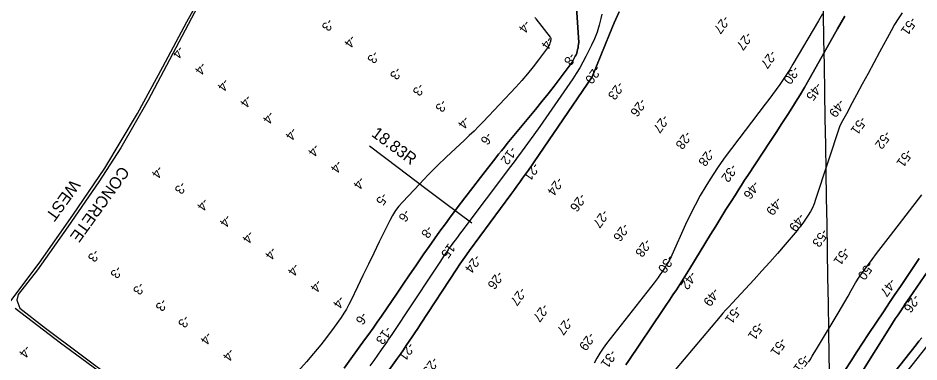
# Model space of a CAD drawing. Extents: x 3879599 to 3900814, y 146526 to 168888.
# Drawn here: x 3891140 to 3894369, y 158633 to 159864 of the extents above; entities that cross this region are included whole.
import ezdxf

# ---------------------------------------------------------------- set-up
doc = ezdxf.new("R2010")
doc.units = 0
for name, color, linetype in [('V-GRID-MAJR', 7, 'Continuous'), ('V-LEVE-TOET', 7, 'Continuous'), ('V-RIVR-JETY', 7, 'Continuous'), ('V-RIVR-RANG', 7, 'Continuous'), ('V-STRM-FMON', 7, 'Continuous'), ('V-TOPO-DPTH', 7, 'Continuous'), ('V-TOPO-MAJR', 7, 'Continuous'), ('V-TOPO-MINR', 7, 'Continuous')]:
    doc.layers.add(name, color=color, linetype=linetype)

msp = doc.modelspace()

# ---------------------------------------------------------------- linework, layer by layer
at = {"layer": 'V-GRID-MAJR'}
msp.add_spline([(3894134.7, 153416.7), (3894080.4, 156663.6), (3893979, 162723.9), (3893946.7, 164659.1)], degree=3, dxfattribs=at)
at = {"layer": 'V-LEVE-TOET'}
msp.add_lwpolyline([(3892766.9, 159129.2), (3892668.1, 159203), (3892601.4, 159252), (3892503, 159328.2), (3892400.2, 159404.9)], dxfattribs=at)
at = {"layer": 'V-RIVR-JETY'}
for points in [[(3890311.8, 157772.1), (3890351.4, 157824), (3890391.9, 157878.3), (3890469.7, 157970.5), (3890554, 158087), (3890601.4, 158142.3), (3890711.2, 158292.3), (3890848.1, 158493.3), (3890978.8, 158672.5), (3891093.1, 158822.5), (3891215.9, 158985.9), (3891337.2, 159158.7), (3891451.6, 159326.6), (3891568.1, 159522.2), (3891659.2, 159689.7), (3891745.2, 159850.3), (3891815.3, 159977.8)], [(3891795.7, 159927.3), (3891716.1, 159777.6), (3891607, 159570.1), (3891508.5, 159399.1), (3891430.5, 159277.6), (3891318.7, 159116.7), (3891209.8, 158962.1), (3891141.4, 158873.8), (3891135.9, 158853.5), (3891147.1, 158824.7), (3891238.4, 158753.9), (3891490.2, 158565.7), (3891632.8, 158455.9), (3891627.8, 158448.5), (3891486.2, 158557.8), (3891292.7, 158700.1), (3891130.8, 158823.8)]]:
    msp.add_lwpolyline(points, dxfattribs=at)
at = {"layer": 'V-TOPO-DPTH'}
for points in [[(3892308.5, 158610.4), (3892333.3, 158643.9), (3892382.5, 158711.3), (3892397.8, 158732.5), (3892413, 158753.8), (3892427.9, 158775.3), (3892442.7, 158796.9), (3892498.6, 158879.1), (3892520.8, 158911.7), (3892543, 158944.2), (3892565.3, 158976.6), (3892587.6, 159009.1), (3892594.7, 159019.4), (3892613.7, 159046.5), (3892632.8, 159073.6), (3892652.2, 159100.5), (3892671.7, 159127.2), (3892686.7, 159147.6), (3892714, 159184.4), (3892741.6, 159220.9), (3892769.5, 159257.3), (3892797.5, 159293.4), (3892852.2, 159363.2), (3892862.5, 159376.2), (3892872.8, 159389.1), (3892883.2, 159401.9), (3892893.6, 159414.6), (3892995.1, 159537.3), (3893017.5, 159564.8), (3893039.7, 159592.5), (3893061.5, 159620.6), (3893083.1, 159648.8), (3893119, 159696.5), (3893122.3, 159701.1), (3893125.5, 159705.8), (3893128.4, 159710.7), (3893131.1, 159715.6), (3893137.3, 159727.3), (3893140, 159733), (3893142.4, 159738.9), (3893144.2, 159745), (3893145.7, 159751.2), (3893146.9, 159757.5), (3893147.9, 159763.9), (3893148.7, 159770.2), (3893149.3, 159776.6), (3893127.6, 160119)], [(3893293.9, 159887), (3893276.9, 159847), (3893260.2, 159806.9), (3893197.7, 159653.6), (3892990.3, 159349.7), (3892980, 159334.8), (3892969.7, 159320), (3892959.2, 159305.3), (3892948.6, 159290.7), (3892937.9, 159276.2), (3892927.2, 159261.6), (3892916.6, 159247.1), (3892905.9, 159232.5), (3892758.5, 159031.9), (3892746.8, 159015.8), (3892735.3, 158999.5), (3892724.1, 158983.1), (3892713, 158966.6), (3892582.6, 158768.2), (3892572.5, 158752.8), (3892562.3, 158737.4), (3892552.2, 158722), (3892542, 158706.6), (3892531.8, 158691.3), (3892521.4, 158676.1), (3892510.9, 158661), (3892500.2, 158645.9), (3892307.5, 158376.6)], [(3892307.5, 158376.6), (3892500.2, 158645.9), (3892510.9, 158661), (3892521.4, 158676.1), (3892531.8, 158691.3), (3892542, 158706.6), (3892552.2, 158722), (3892562.3, 158737.4), (3892572.5, 158752.8), (3892582.6, 158768.2), (3892713, 158966.6), (3892724.1, 158983.1), (3892735.3, 158999.5), (3892746.8, 159015.8), (3892758.5, 159031.9), (3892905.9, 159232.5), (3892916.6, 159247.1), (3892927.2, 159261.6), (3892937.9, 159276.2), (3892948.6, 159290.7), (3892959.2, 159305.3), (3892969.7, 159320), (3892980, 159334.8), (3892990.3, 159349.7), (3893197.7, 159653.6), (3893260.2, 159806.9), (3893276.9, 159847), (3893293.9, 159887)], [(3894023.5, 159879.5), (3894009, 159854.8), (3893916.9, 159698.5), (3893905.6, 159680), (3893894, 159661.6), (3893881.9, 159643.6), (3893869.6, 159625.7), (3893856.9, 159608.1), (3893844.1, 159590.5), (3893831.2, 159573.1), (3893818.1, 159555.7), (3893674.7, 159366.6), (3893660.4, 159347.2), (3893646.5, 159327.5), (3893633.3, 159307.4), (3893620.4, 159287), (3893604.9, 159261.8), (3893585.2, 159228.3), (3893566.4, 159194.3), (3893549, 159159.6), (3893532.4, 159124.5), (3893483.2, 159014.9), (3893480.4, 159009), (3893477.5, 159003.2), (3893474.4, 158997.4), (3893471.1, 158991.7), (3893466.4, 158983.7), (3893464.4, 158980.4), (3893462.4, 158977.2), (3893460.3, 158974), (3893459.7, 158973), (3893459.1, 158972.1), (3893447.2, 158954.4), (3893440.6, 158944.7), (3893433.8, 158935), (3893426.8, 158925.6), (3893419.6, 158916.2), (3893249.2, 158698.6), (3893236.8, 158681.8), (3893225, 158664.5), (3893214.3, 158646.6), (3893204.3, 158628.3)], [(3894023.5, 159879.5), (3894009, 159854.8), (3893916.9, 159698.5), (3893905.6, 159680), (3893894, 159661.6), (3893881.9, 159643.6), (3893869.6, 159625.7), (3893856.9, 159608.1), (3893844.1, 159590.5), (3893831.2, 159573.1), (3893818.1, 159555.7), (3893674.7, 159366.6), (3893660.4, 159347.2), (3893646.5, 159327.5), (3893633.3, 159307.4), (3893620.4, 159287), (3893604.9, 159261.8), (3893585.2, 159228.3), (3893566.4, 159194.3), (3893549, 159159.6), (3893532.4, 159124.5), (3893483.2, 159014.9), (3893480.4, 159009), (3893477.5, 159003.2), (3893474.4, 158997.4), (3893471.1, 158991.7), (3893466.4, 158983.7), (3893464.4, 158980.4), (3893462.4, 158977.2), (3893460.3, 158974), (3893459.7, 158973), (3893459.1, 158972.1), (3893447.2, 158954.4), (3893440.6, 158944.7), (3893433.8, 158935), (3893426.8, 158925.6), (3893419.6, 158916.2), (3893249.2, 158698.6), (3893236.8, 158681.8), (3893225, 158664.5), (3893214.3, 158646.6), (3893204.3, 158628.3)], [(3893317.9, 158622.4), (3893328.5, 158638.1), (3893449.6, 158816.4), (3893462.2, 158835), (3893474.6, 158853.7), (3893487, 158872.4), (3893499.3, 158891.2), (3893511.4, 158910.1), (3893523.4, 158929), (3893535.3, 158948), (3893547.1, 158967.1), (3893621.9, 159089.4), (3893640.2, 159119), (3893658.5, 159148.6), (3893676.9, 159178), (3893695.4, 159207.4), (3893710.7, 159231.5), (3893721.7, 159248.8), (3893732.8, 159266), (3893744, 159283.2), (3893755.3, 159300.3), (3893836, 159422.4), (3893856.9, 159454.3), (3893877.7, 159486.4), (3893898.2, 159518.6), (3893918.6, 159550.9), (3893926, 159562.7), (3893942.4, 159589.3), (3893958.5, 159616.1), (3893974.2, 159643), (3893989.7, 159670.1), (3894077.2, 159825.8), (3894089.9, 159848.4), (3894102.8, 159871)], [(3893317.9, 158622.4), (3893328.5, 158638.1), (3893449.6, 158816.4), (3893462.2, 158835), (3893474.6, 158853.7), (3893487, 158872.4), (3893499.3, 158891.2), (3893511.4, 158910.1), (3893523.4, 158929), (3893535.3, 158948), (3893547.1, 158967.1), (3893621.9, 159089.4), (3893640.2, 159119), (3893658.5, 159148.6), (3893676.9, 159178), (3893695.4, 159207.4), (3893710.7, 159231.5), (3893721.7, 159248.8), (3893732.8, 159266), (3893744, 159283.2), (3893755.3, 159300.3), (3893836, 159422.4), (3893856.9, 159454.3), (3893877.7, 159486.4), (3893898.2, 159518.6), (3893918.6, 159550.9), (3893926, 159562.7), (3893942.4, 159589.3), (3893958.5, 159616.1), (3893974.2, 159643), (3893989.7, 159670.1), (3894077.2, 159825.8), (3894089.9, 159848.4), (3894102.8, 159871)], [(3894113.3, 158516.1), (3894264.7, 158756.5), (3894274.2, 158771.5), (3894283.8, 158786.5), (3894293.5, 158801.4), (3894303.2, 158816.2), (3894311.7, 158829), (3894317.3, 158837.4), (3894322.9, 158845.8), (3894328.6, 158854.2), (3894334.2, 158862.5), (3894544.4, 159168.1)], [(3894544.4, 159168.1), (3894334.2, 158862.5), (3894328.6, 158854.2), (3894322.9, 158845.8), (3894317.3, 158837.4), (3894311.7, 158829), (3894303.2, 158816.2), (3894293.5, 158801.4), (3894283.8, 158786.5), (3894274.2, 158771.5), (3894264.7, 158756.5), (3894113.3, 158516.1)], [(3894105.7, 158605.8), (3894125.9, 158637.1), (3894146.1, 158668.4), (3894166.5, 158699.5), (3894187.1, 158730.6), (3894244, 158816.2), (3894263.2, 158845.1), (3894282.5, 158873.9), (3894301.9, 158902.8), (3894321.3, 158931.5), (3894325.8, 158938.3), (3894347.4, 158970.5), (3894368.8, 159002.8)], [(3894368.8, 159002.8), (3894347.4, 158970.5), (3894325.8, 158938.3), (3894321.3, 158931.5), (3894301.9, 158902.8), (3894282.5, 158873.9), (3894263.2, 158845.1), (3894244, 158816.2), (3894187.1, 158730.6), (3894166.5, 158699.5), (3894146.1, 158668.4), (3894125.9, 158637.1), (3894105.7, 158605.8)], [(3894378.3, 158719.5), (3894368.2, 158706.8), (3894358.2, 158694), (3894196.5, 158488.7)], [(3894378.3, 158719.5), (3894368.2, 158706.8), (3894358.2, 158694), (3894196.5, 158488.7)]]:
    msp.add_lwpolyline(points, dxfattribs=at)
at = {"layer": 'V-TOPO-MAJR'}
for points in [[(3894308.1, 159882.7), (3894294, 159862), (3894280.9, 159840.7), (3894268.5, 159818.9), (3894227, 159741.7), (3894206.5, 159703.6), (3894186, 159665.4), (3894165.5, 159627.3), (3894145.1, 159589.1), (3894122.6, 159547.2), (3894113.4, 159530), (3894104.1, 159512.8), (3894094.8, 159495.7), (3894085.4, 159478.5), (3893997.6, 159214.4), (3893992.9, 159199.4), (3893987.2, 159184.9), (3893980, 159171.1), (3893971.8, 159157.8), (3893952.5, 159130.1), (3893947.7, 159123.3), (3893942.7, 159116.7), (3893937.5, 159110.2), (3893932.2, 159103.8), (3893888.8, 159053), (3893861.5, 159021.4), (3893833.9, 158990.1), (3893805.9, 158959.1), (3893777.7, 158928.4), (3893699, 158843.7), (3893688, 158831.7), (3893677.1, 158819.6), (3893666.4, 158807.3), (3893655.8, 158794.9), (3893495.5, 158604.8)], [(3893972.7, 158631.3), (3893978.4, 158640.7), (3893986, 158653.2), (3893993.5, 158665.6), (3894001, 158678.1), (3894008.5, 158690.6), (3894078.7, 158807.9), (3894090.7, 158828.1), (3894102.6, 158848.3), (3894114.4, 158868.6), (3894126.1, 158889), (3894141.4, 158915.6), (3894145.5, 158922.6), (3894149.8, 158929.5), (3894154.2, 158936.3), (3894158.8, 158943), (3894163.4, 158949.6), (3894165.8, 158952.9), (3894168.1, 158956.2), (3894170.5, 158959.5), (3894173, 158962.8), (3894200.5, 158999.5), (3894216.8, 159021.1), (3894233.1, 159042.7), (3894249.5, 159064.2), (3894266.1, 159085.6), (3894378.5, 159230.8)]]:
    msp.add_lwpolyline(points, dxfattribs=at)
at = {"layer": 'V-TOPO-MINR'}
for points in [[(3893127.6, 160119), (3893149.3, 159776.6), (3893148.7, 159770.2), (3893147.9, 159763.9), (3893146.9, 159757.5), (3893145.7, 159751.2), (3893144.2, 159745), (3893142.4, 159738.9), (3893140, 159733), (3893137.3, 159727.3), (3893131.1, 159715.6), (3893128.4, 159710.7), (3893125.5, 159705.8), (3893122.3, 159701.1), (3893119, 159696.5), (3893083.1, 159648.8), (3893061.5, 159620.6), (3893039.7, 159592.5), (3893017.5, 159564.8), (3892995.1, 159537.3), (3892893.6, 159414.6), (3892883.2, 159401.9), (3892872.8, 159389.1), (3892862.5, 159376.2), (3892852.2, 159363.2), (3892797.5, 159293.4), (3892769.5, 159257.3), (3892741.6, 159220.9), (3892714, 159184.4), (3892686.7, 159147.6), (3892671.7, 159127.2), (3892652.2, 159100.5), (3892632.8, 159073.6), (3892613.7, 159046.5), (3892594.7, 159019.4), (3892587.6, 159009.1), (3892565.3, 158976.6), (3892543, 158944.2), (3892520.8, 158911.7), (3892498.6, 158879.1), (3892442.7, 158796.9), (3892427.9, 158775.3), (3892413, 158753.8), (3892397.8, 158732.5), (3892382.5, 158711.3), (3892333.3, 158643.9), (3892308.5, 158610.4)], [(3892992.1, 159866.7), (3892994.2, 159864.3), (3892996.2, 159861.8), (3893046.7, 159796.3), (3893047.8, 159794.6), (3893049.1, 159790.9), (3893049.4, 159786.8), (3893048.9, 159782.8), (3893048.4, 159780.8), (3893046.4, 159774.4), (3893044.7, 159769.9), (3893042.8, 159765.5), (3893040.4, 159761.3), (3893037.7, 159757.3), (3893005.5, 159714.2), (3892986, 159689.2), (3892966, 159664.5), (3892945.2, 159640.6), (3892923.9, 159617.1), (3892807.1, 159493), (3892790.8, 159476.1), (3892774.3, 159459.4), (3892757.4, 159443.1), (3892740.2, 159427), (3892707.8, 159397.3), (3892674.7, 159366.1), (3892642, 159334.5), (3892609.9, 159302.3), (3892578.4, 159269.5), (3892518.8, 159206.4), (3892505.4, 159190.8), (3892493.1, 159174.6), (3892482.2, 159157.3), (3892472.3, 159139.3), (3892434.9, 159062.8), (3892415.3, 159022.6), (3892395.8, 158982.5), (3892376.5, 158942.2), (3892357.2, 158902), (3892334.3, 158853.9), (3892326.1, 158837.9), (3892317.4, 158822.2), (3892307.9, 158806.9), (3892297.9, 158792), (3892272.8, 158756.7), (3892249.2, 158724.7), (3892225, 158693.3), (3892199.7, 158662.8), (3892173.7, 158632.8), (3892090.5, 158539.9)], [(3893293.9, 159887), (3893276.9, 159847), (3893260.2, 159806.9), (3893197.7, 159653.6), (3892990.3, 159349.7), (3892980, 159334.8), (3892969.7, 159320), (3892959.2, 159305.3), (3892948.6, 159290.7), (3892937.9, 159276.2), (3892927.2, 159261.6), (3892916.6, 159247.1), (3892905.9, 159232.5), (3892758.5, 159031.9), (3892746.8, 159015.8), (3892735.3, 158999.5), (3892724.1, 158983.1), (3892713, 158966.6), (3892582.6, 158768.2), (3892572.5, 158752.8), (3892562.3, 158737.4), (3892552.2, 158722), (3892542, 158706.6), (3892531.8, 158691.3), (3892521.4, 158676.1), (3892510.9, 158661), (3892500.2, 158645.9), (3892307.5, 158376.6)], [(3893232.4, 159878.7), (3893228.9, 159863.1), (3893222.5, 159838.3), (3893215, 159813.9), (3893205.6, 159790.1), (3893195, 159766.8), (3893175, 159726.6), (3893164.2, 159706), (3893152.9, 159685.8), (3893140.7, 159666.1), (3893128, 159646.7), (3893053.6, 159538.2), (3893032.1, 159507.2), (3893010.4, 159476.4), (3892988.3, 159445.7), (3892966.1, 159415.2), (3892937.2, 159376.1), (3892929.2, 159365.3), (3892921.3, 159354.5), (3892913.2, 159343.8), (3892905.2, 159333.1), (3892730.6, 159101.1), (3892722.6, 159090.5), (3892714.7, 159079.8), (3892706.8, 159069.2), (3892698.9, 159058.5), (3892685.3, 159040.1), (3892683.2, 159037.2), (3892681.2, 159034.2), (3892663.7, 159008.5), (3892654, 158994.1), (3892644.3, 158979.7), (3892634.7, 158965.2), (3892625.1, 158950.8), (3892479.9, 158731), (3892474.2, 158722.5), (3892468.5, 158714), (3892462.7, 158705.6), (3892456.9, 158697.2), (3892441.8, 158675.5), (3892428.3, 158656.4), (3892414.8, 158637.3), (3892401.1, 158618.3)], [(3894023.5, 159879.5), (3894009, 159854.8), (3893916.9, 159698.5), (3893905.6, 159680), (3893894, 159661.6), (3893881.9, 159643.6), (3893869.6, 159625.7), (3893856.9, 159608.1), (3893844.1, 159590.5), (3893831.2, 159573.1), (3893818.1, 159555.7), (3893674.7, 159366.6), (3893660.4, 159347.2), (3893646.5, 159327.5), (3893633.3, 159307.4), (3893620.4, 159287), (3893604.9, 159261.8), (3893585.2, 159228.3), (3893566.4, 159194.3), (3893549, 159159.6), (3893532.4, 159124.5), (3893483.2, 159014.9), (3893480.4, 159009), (3893477.5, 159003.2), (3893474.4, 158997.4), (3893471.1, 158991.7), (3893466.4, 158983.7), (3893464.4, 158980.4), (3893462.4, 158977.2), (3893460.3, 158974), (3893459.7, 158973), (3893459.1, 158972.1), (3893447.2, 158954.4), (3893440.6, 158944.7), (3893433.8, 158935), (3893426.8, 158925.6), (3893419.6, 158916.2), (3893249.2, 158698.6), (3893236.8, 158681.8), (3893225, 158664.5), (3893214.3, 158646.6), (3893204.3, 158628.3)], [(3894102.8, 159871), (3894089.9, 159848.4), (3894077.2, 159825.8), (3893989.7, 159670.1), (3893974.2, 159643), (3893958.5, 159616.1), (3893942.4, 159589.3), (3893926, 159562.7), (3893918.6, 159550.9), (3893898.2, 159518.6), (3893877.7, 159486.4), (3893856.9, 159454.3), (3893836, 159422.4), (3893755.3, 159300.3), (3893744, 159283.2), (3893732.8, 159266), (3893721.7, 159248.8), (3893710.7, 159231.5), (3893695.4, 159207.4), (3893676.9, 159178), (3893658.5, 159148.6), (3893640.2, 159119), (3893621.9, 159089.4), (3893547.1, 158967.1), (3893535.3, 158948), (3893523.4, 158929), (3893511.4, 158910.1), (3893499.3, 158891.2), (3893487, 158872.4), (3893474.6, 158853.7), (3893462.2, 158835), (3893449.6, 158816.4), (3893328.5, 158638.1), (3893317.9, 158622.4)], [(3894113.3, 158516.1), (3894264.7, 158756.5), (3894274.2, 158771.5), (3894283.8, 158786.5), (3894293.5, 158801.4), (3894303.2, 158816.2), (3894311.7, 158829), (3894317.3, 158837.4), (3894322.9, 158845.8), (3894328.6, 158854.2), (3894334.2, 158862.5), (3894544.4, 159168.1)], [(3894105.7, 158605.8), (3894125.9, 158637.1), (3894146.1, 158668.4), (3894166.5, 158699.5), (3894187.1, 158730.6), (3894244, 158816.2), (3894263.2, 158845.1), (3894282.5, 158873.9), (3894301.9, 158902.8), (3894321.3, 158931.5), (3894325.8, 158938.3), (3894347.4, 158970.5), (3894368.8, 159002.8)], [(3894196.5, 158488.7), (3894358.2, 158694), (3894368.2, 158706.8), (3894378.3, 158719.5)], [(3894204.8, 158444.9), (3894420.9, 158718.3)]]:
    msp.add_lwpolyline(points, dxfattribs=at)

# ---------------------------------------------------------------- texts
at = {"layer": 'V-RIVR-JETY'}
for s, p in [('CONCRETE', (3891508.9, 159337)), ('WEST', (3891332.4, 159289.3))]:
    msp.add_text(s, height=42, rotation=234.222, dxfattribs=at).set_placement(p)
at = {"layer": 'V-RIVR-RANG'}
for s, rotation, p in [('-27', 233.9183, (3893668.8, 159875.7)), ('-51', 234.2611, (3894339, 159870.7)), ('-3', 234.3883, (3892249.6, 159865.3)), ('-4', 233.9783, (3892955.5, 159859.1)), ('-4', 234.3883, (3892330, 159805.9)), ('-27', 233.9183, (3893749.8, 159817)), ('-4', 233.9783, (3893036.5, 159800.5)), ('-4', 234.0183, (3891714.1, 159767.3)), ('-3', 234.3883, (3892412.5, 159749.3)), ('-8', 233.9783, (3893117.7, 159742.2)), ('-27', 234.0574, (3893836.6, 159751.5)), ('-4', 234.0183, (3891795.2, 159708.8)), ('-3', 234.3883, (3892493.9, 159691.3)), ('-20', 233.9783, (3893208.3, 159696.7)), ('-30', 234.0574, (3893918.9, 159695.2)), ('-4', 234.0183, (3891876.3, 159650.2)), ('-3', 234.3883, (3892575.4, 159633.2)), ('-23', 233.9783, (3893290, 159639.1)), ('-45', 234.0574, (3893999.9, 159636)), ('-4', 234.0183, (3891957.3, 159591.7)), ('-26', 233.9783, (3893370.1, 159579.2)), ('-49', 234.0574, (3894081.7, 159576.8)), ('-3', 234.3883, (3892656.8, 159575.2)), ('-4', 234.0183, (3892038.4, 159533.2)), ('-4', 234.3883, (3892737.2, 159515.8)), ('-27', 233.9783, (3893451.2, 159520.6)), ('-51', 234.0574, (3894159.6, 159514.5)), ('-4', 234.0183, (3892119.5, 159474.6)), ('-6', 234.3883, (3892818.8, 159457.9)), ('-28', 233.9783, (3893532.3, 159462.2)), ('-52', 234.0574, (3894246.8, 159462.8)), ('-4', 234.0183, (3892200.5, 159416.1)), ('-12', 234.3883, (3892905.4, 159407.1)), ('-28', 234.1223, (3893613.7, 159401.3)), ('-51', 234.0574, (3894323.7, 159398.1)), ('-4', 234.0183, (3892281.6, 159357.5)), ('-4', 234.2083, (3891640.2, 159338.3)), ('-21', 234.3883, (3892987, 159349.2)), ('-32', 234.1223, (3893696.1, 159344.3)), ('-4', 234.0183, (3892362.7, 159299)), ('-24', 234.3883, (3893072.4, 159296.8)), ('-3', 234.2083, (3891722.5, 159281.4)), ('-46', 234.1223, (3893775.4, 159283.9)), ('-4', 234.2083, (3891802.7, 159221.8)), ('-5', 234.0183, (3892444.3, 159241.2)), ('-26', 234.3883, (3893153.9, 159238.9)), ('-49', 234.1223, (3893856.6, 159226)), ('-4', 234.2083, (3891884, 159163.5)), ('-6', 234.0183, (3892524.9, 159182)), ('-27', 234.3883, (3893235.4, 159180.8)), ('-49', 234.1223, (3893938.8, 159167.5)), ('-26', 234.5325, (3893308.4, 159132.1)), ('-4', 234.2083, (3891965.2, 159105.2)), ('-8', 234.0183, (3892606.1, 159123.6)), ('-53', 234.1223, (3894021.9, 159111.8)), ('-15', 234.0183, (3892692, 159071.7)), ('-28', 234.5325, (3893387.5, 159076.2)), ('-3', 233.7983, (3891411.7, 159038.3)), ('-4', 234.2083, (3892046.5, 159046.9)), ('-51', 234.1223, (3894098.3, 159046.8)), ('-24', 234.0183, (3892777.5, 159019.3)), ('-30', 234.5325, (3893468.9, 159018.7)), ('-3', 233.7983, (3891492.5, 158979.4)), ('-4', 234.2083, (3892127.8, 158988.6)), ('-50', 234.1223, (3894184.9, 158994.3)), ('-4', 234.2083, (3892209, 158930.4)), ('-26', 234.0183, (3892858.6, 158960.8)), ('-42', 234.5325, (3893549.9, 158959.9)), ('-47', 234.1223, (3894264.5, 158934.6)), ('-3', 233.7983, (3891573.4, 158920.6)), ('-27', 234.0183, (3892939.7, 158902.3)), ('-49', 234.5325, (3893631.3, 158900.2)), ('-4', 234.2083, (3892290.3, 158872.1)), ('-26', 234.1223, (3894349.7, 158877.2)), ('-3', 233.7983, (3891654.2, 158861.7)), ('-27', 234.0183, (3893020.8, 158843.7)), ('-51', 234.5325, (3893709, 158837.7)), ('-3', 233.7983, (3891735, 158802.8)), ('-6', 234.2083, (3892371.6, 158813.9)), ('-27', 234.1644, (3893105.7, 158797.1)), ('-51', 234.5325, (3893791, 158779.3)), ('-4', 233.7983, (3891814.9, 158742.6)), ('-13', 234.2083, (3892458.3, 158763.1)), ('-29', 234.1644, (3893186.5, 158741.4)), ('-21', 234.2083, (3892539.5, 158704.7)), ('-51', 234.5325, (3893871.9, 158721.7)), ('-4', 234.0683, (3891165.3, 158695.3)), ('-4', 233.7983, (3891895.7, 158683.7)), ('-31', 234.1644, (3893264, 158678.9)), ('-25', 234.2083, (3892625.3, 158652.7)), ('-51', 234.5325, (3893954.1, 158663.2))]:
    msp.add_text(s, height=33.5, rotation=rotation, dxfattribs=at).set_placement(p)
at = {"layer": 'V-STRM-FMON'}
msp.add_text('18.83R', height=42, rotation=323.5117, dxfattribs=at).set_placement((3892403.8, 159443.6))

doc.saveas('drawing.dxf')
